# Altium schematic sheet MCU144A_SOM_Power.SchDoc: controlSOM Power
size 431 x 279 mm; Date: Not shown in title block; ApprovedBy: Not shown in title block; CheckedBy: Not shown in title block; Author: Not shown in title block; CompanyName: Not shown in title block; DrawnBy: Gustavo Martinez; Engineer: Not shown in title block; Organization: Not shown in title block; Address1: Not shown in title block; Address2: Not shown in title block; Address3: Not shown in title block; Address4: Not shown in title block; DocumentNumber: 6; Revision: Use project parameter SCH_Rev; SheetNumber: 5; SheetTotal: 8; PageSetup: Record=PageOptions¦CenterHorizontal=True¦CenterVertical=True¦PrintScale=1.00¦XCorrection=1.00¦YCorrection=1.00¦PrintKind=0¦BorderSize=5000000¦LeftOffset=0¦BottomOffset=0¦Orientation=2¦PaperLength=1000¦PaperWidth=1000¦Scale=100¦PaperSource=15¦PrintQuality=600¦MediaType=1¦DitherType=10¦PaperKind=Letter¦PrintScaleMode=1
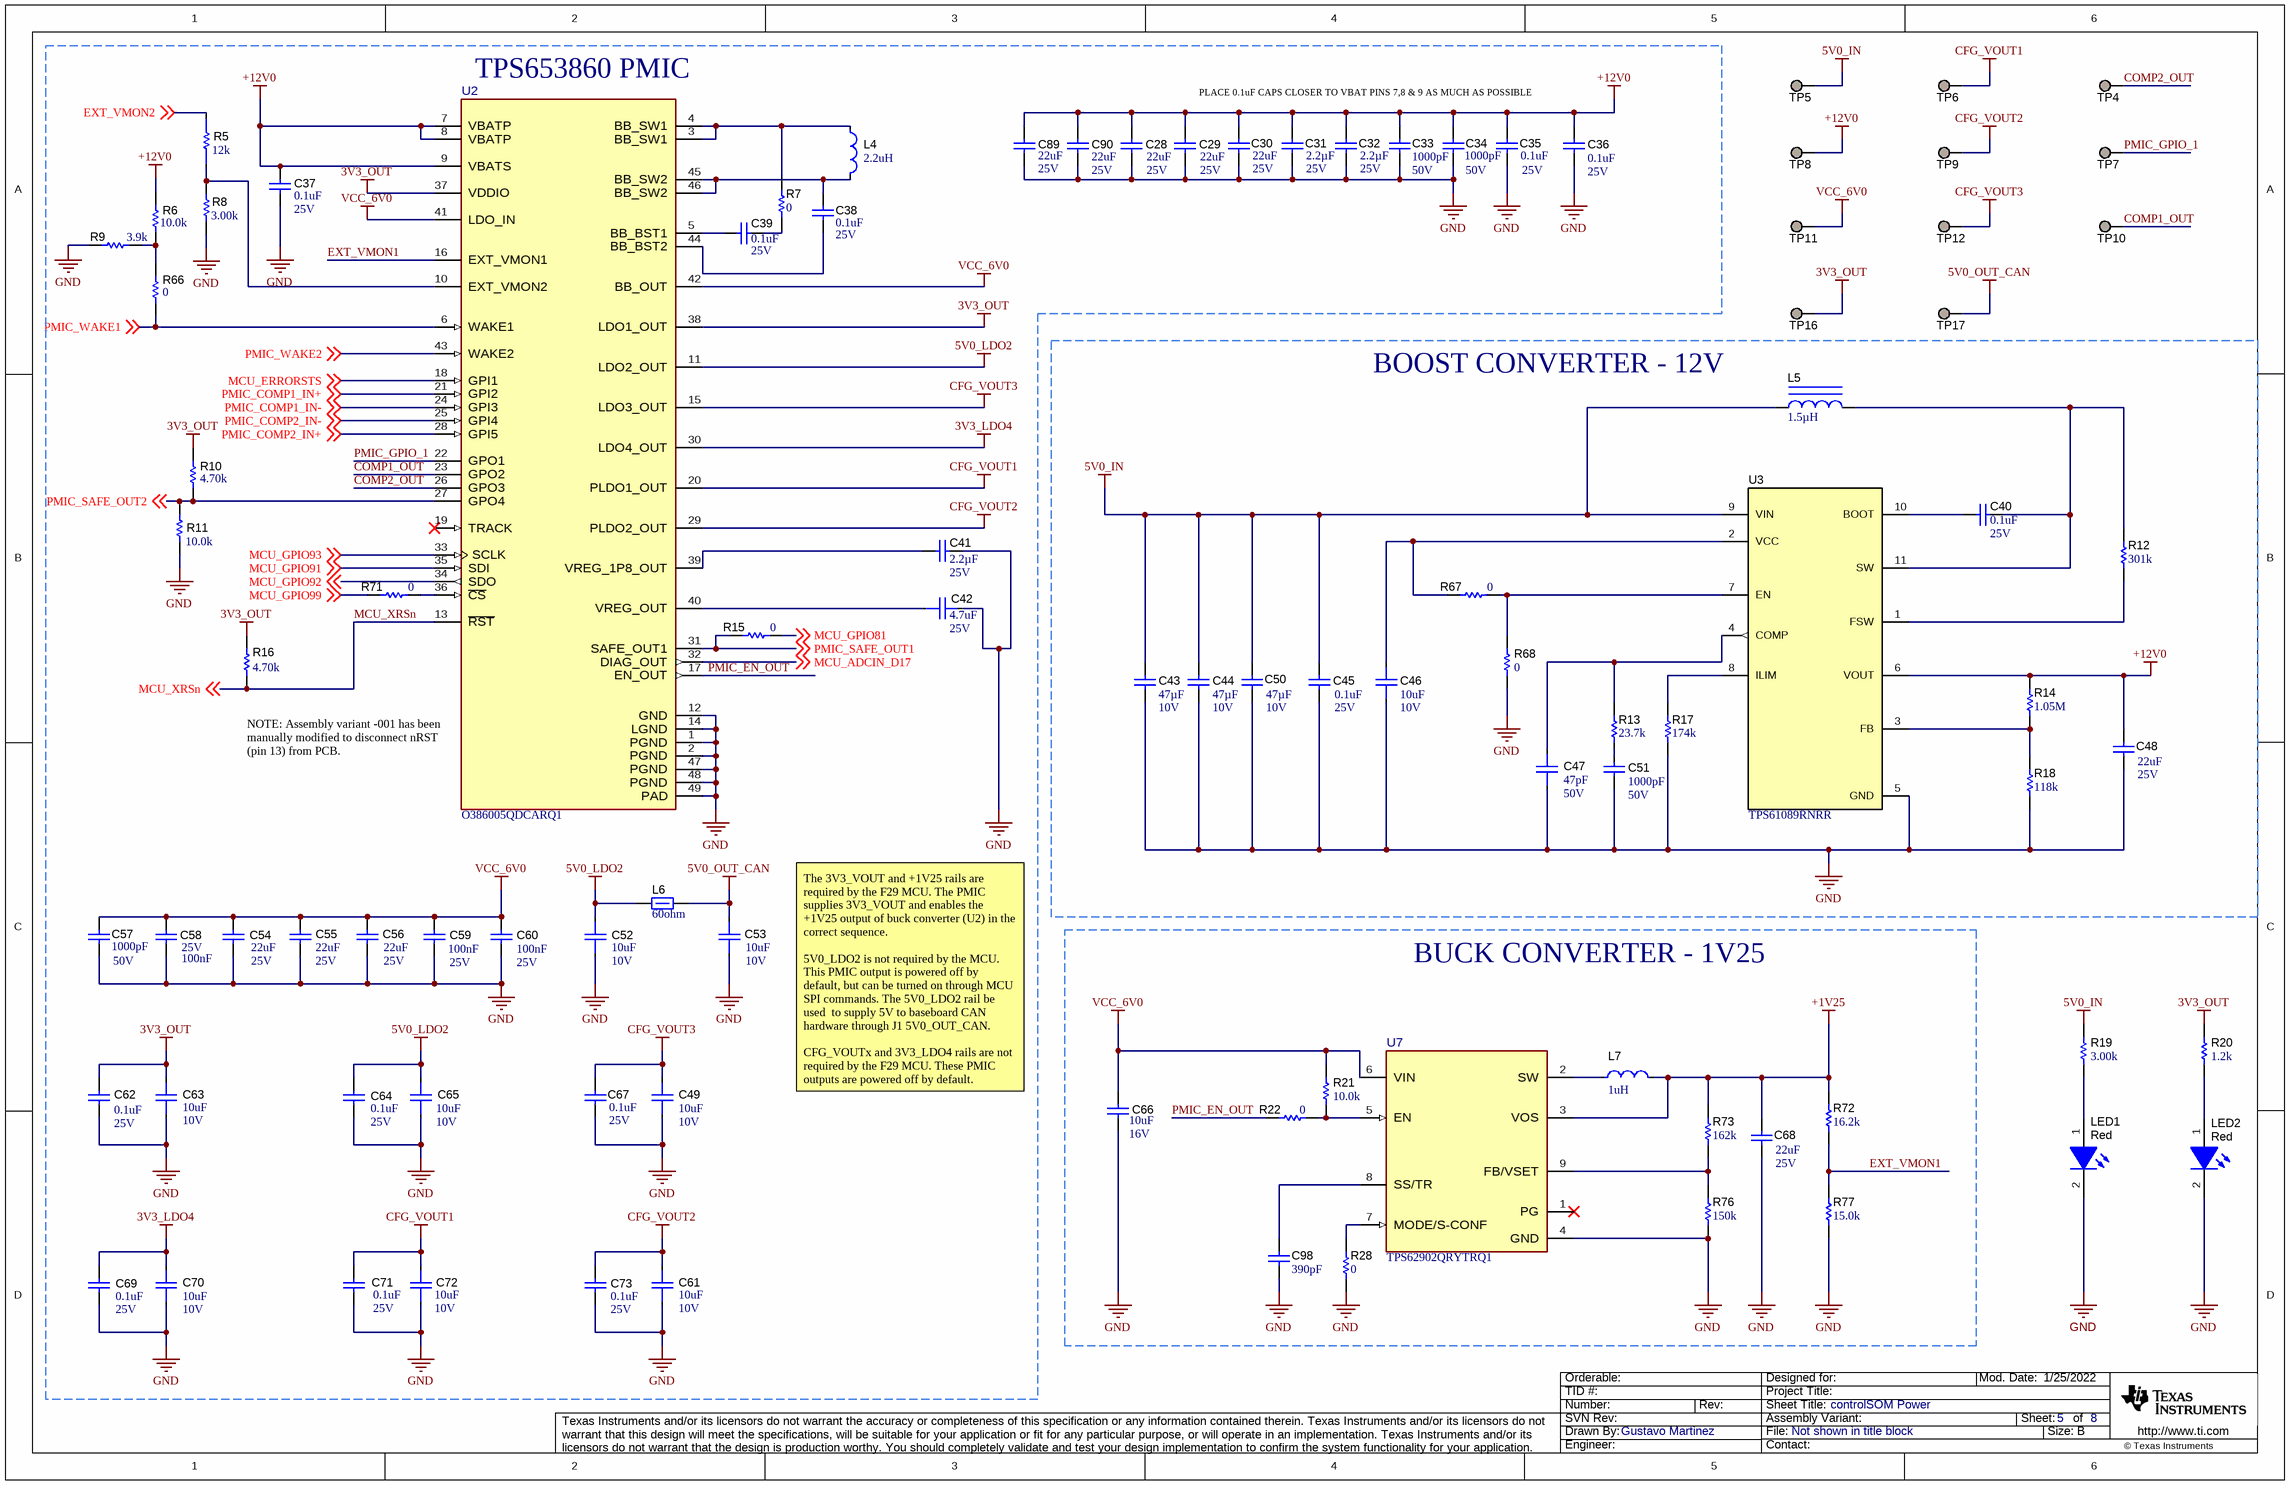
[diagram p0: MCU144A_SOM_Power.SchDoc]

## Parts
C28  VDC_V: 25V  ValueDisplayed: 22uF  [0805_HV]  (hidden comment: GRM21BR61E226ME44L)
C29  VDC_V: 25V  ValueDisplayed: 22uF  [0805_HV]  (hidden comment: GRM21BR61E226ME44L)
C30  VDC_V: 25V  ValueDisplayed: 22uF  [0805_HV]  (hidden comment: GRM21BR61E226ME44L)
C31  VDC_V: 25V  ValueDisplayed: 2.2µF  [0402]  (hidden comment: GRM155R61E225ME15D)
C32  VDC_V: 25V  ValueDisplayed: 2.2µF  [0402]  (hidden comment: GRM155R61E225ME15D)
C33  VDC_V: 50V  ValueDisplayed: 1000pF  [0402]  (hidden comment: GRM1555C1H102JA01D)
C34  VDC_V: 50V  ValueDisplayed: 1000pF  [0402]  (hidden comment: GRM1555C1H102JA01D)
C35  VDC_V: 25V  ValueDisplayed: 0.1uF  [0402]  (hidden comment: GRM155R71E104KE14D)
C36  VDC_V: 25V  ValueDisplayed: 0.1uF  [0402]  (hidden comment: GRM155R71E104KE14D)
C37  VDC_V: 25V  ValueDisplayed: 0.1uF  [0402]  (hidden comment: GRM155R71E104KE14D)
C38  VDC_V: 25V  ValueDisplayed: 0.1uF  [0402]  (hidden comment: GRM155R71E104KE14D)
C39  VDC_V: 25V  ValueDisplayed: 0.1uF  [0402]  (hidden comment: GRM155R71E104KE14D)
C40  Value2: 25V  ValueDisplayed: 0.1uF  [0402]  (hidden comment: GRM155R71E104KE14D)
C41  VDC_V: 25V  ValueDisplayed: 2.2µF  [0402]  (hidden comment: GRM155R61E225ME15D)
C42  ValueDisplayed: 4.7uF  VDC_V: 25V  [FP-GRM155C61E475ME15D_0402-MFG]  (hidden comment: GRM155C61E475ME15D)
C43  VDC_V: 10V  ValueDisplayed: 47µF  [0805_HV]  (hidden comment: GRM21BR61A476ME15L)
C44  VDC_V: 10V  ValueDisplayed: 47µF  [0805_HV]  (hidden comment: GRM21BR61A476ME15L)
C45  VDC_V: 25V  ValueDisplayed: 0.1uF  [0402]  (hidden comment: GRM155R71E104KE14D)
C46  VDC_V: 10V  ValueDisplayed: 10uF  [FP-GRM155R61A106ME18D_0402-MFG]  (hidden comment: GRM155R61A106ME18D)
C47  ValueDisplayed: 47pF  VDC_V: 50V  [FP-GJM1555C1H470JB01D_0402-MFG]  (hidden comment: GJM1555C1H470JB01D)
C48  VDC_V: 25V  ValueDisplayed: 22uF  [0805_HV]  (hidden comment: GRM21BR61E226ME44L)
C49  VDC_V: 10V  ValueDisplayed: 10uF  [FP-GRM155R61A106ME18D_0402-MFG]  (hidden comment: GRM155R61A106ME18D)
C50  VDC_V: 10V  ValueDisplayed: 47µF  [0805_HV]  (hidden comment: GRM21BR61A476ME15L)
C51  VDC_V: 50V  ValueDisplayed: 1000pF  [0402]  (hidden comment: GRM1555C1H102JA01D)
C52  VDC_V: 10V  ValueDisplayed: 10uF  [FP-GRM155R61A106ME18D_0402-MFG]  (hidden comment: GRM155R61A106ME18D)
C53  VDC_V: 10V  ValueDisplayed: 10uF  [FP-GRM155R61A106ME18D_0402-MFG]  (hidden comment: GRM155R61A106ME18D)
C54  VDC_V: 25V  ValueDisplayed: 22uF  [0805_HV]  (hidden comment: GRM21BR61E226ME44L)
C55  VDC_V: 25V  ValueDisplayed: 22uF  [0805_HV]  (hidden comment: GRM21BR61E226ME44L)
C56  VDC_V: 25V  ValueDisplayed: 22uF  [0805_HV]  (hidden comment: GRM21BR61E226ME44L)
C57  VDC_V: 50V  ValueDisplayed: 1000pF  [0402]  (hidden comment: GRM1555C1H102JA01D)
C58  Cap_F: 100nF  VDC_V: 25V  [0402]  (hidden comment: GRM155R71E104KE14D)
C59  Cap_F: 100nF  VDC_V: 25V  [0402]  (hidden comment: GRM155R71E104KE14D)
C60  Cap_F: 100nF  VDC_V: 25V  [0402]  (hidden comment: GRM155R71E104KE14D)
C61  VDC_V: 10V  ValueDisplayed: 10uF  [FP-GRM155R61A106ME18D_0402-MFG]  (hidden comment: GRM155R61A106ME18D)
C62  VDC_V: 25V  ValueDisplayed: 0.1uF  [0402]  (hidden comment: GRM155R71E104KE14D)
C63  VDC_V: 10V  ValueDisplayed: 10uF  [FP-GRM155R61A106ME18D_0402-MFG]  (hidden comment: GRM155R61A106ME18D)
C64  VDC_V: 25V  ValueDisplayed: 0.1uF  [0402]  (hidden comment: GRM155R71E104KE14D)
C65  VDC_V: 10V  ValueDisplayed: 10uF  [FP-GRM155R61A106ME18D_0402-MFG]  (hidden comment: GRM155R61A106ME18D)
C66  VDC_V: 16V  ValueDisplayed: 10uF  [0603]  (hidden comment: GRM188R61C106MAALD)
C67  VDC_V: 25V  ValueDisplayed: 0.1uF  [0402]  (hidden comment: GRM155R71E104KE14D)
C68  VDC_V: 25V  ValueDisplayed: 22uF  [0805_HV]  (hidden comment: GRM21BR61E226ME44L)
C69  VDC_V: 25V  ValueDisplayed: 0.1uF  [0402]  (hidden comment: GRM155R71E104KE14D)
C70  VDC_V: 10V  ValueDisplayed: 10uF  [FP-GRM155R61A106ME18D_0402-MFG]  (hidden comment: GRM155R61A106ME18D)
C71  VDC_V: 25V  ValueDisplayed: 0.1uF  [0402]  (hidden comment: GRM155R71E104KE14D)
C72  VDC_V: 10V  ValueDisplayed: 10uF  [FP-GRM155R61A106ME18D_0402-MFG]  (hidden comment: GRM155R61A106ME18D)
C73  VDC_V: 25V  ValueDisplayed: 0.1uF  [0402]  (hidden comment: GRM155R71E104KE14D)
C89  VDC_V: 25V  ValueDisplayed: 22uF  [0805_HV]  (hidden comment: GRM21BR61E226ME44L)
C90  VDC_V: 25V  ValueDisplayed: 22uF  [0805_HV]  (hidden comment: GRM21BR61E226ME44L)
C98  ValueDisplayed: 390pF  [0402]  (hidden comment: GCM155R71H391KA37D)
L4  value 2.2uH  [FP-SPM7054VT-2R2M-D_SMT_IND_7MM5_7MM0-MFG]  (hidden comment: SPM7054VT-2R2M-D)
L5  ValueDisplayed: 1.5µH  [DFE252012P]  (hidden comment: DFE252012P-1R5M=P2)
L6  60ohm  [0603]
L7  value 1uH  [FP-XGL4030-102MEC_SMD_IND_4MM0_4MM0-MFG]  (hidden comment: XGL4030-102MEC)
LED1  value Red  [APHHS1005_Red]  (hidden comment: APHHS1005SURCK)
LED2  value Red  [APHHS1005_Red]  (hidden comment: APHHS1005SURCK)
R5  value 12k  [FP-RC0402FR-0712KL_0402 (1005 Metric)-MFG]  (hidden comment: RC0402FR-0712KL)
R6  ValueDisplayed: 10.0k  [0402]  (hidden comment: AC0402FR-0710KL)
R7  ValueDisplayed: 0  [0402]  (hidden comment: CRCW04020000Z0ED)
R8  ValueDisplayed: 3.00k  [0402]  (hidden comment: RC0402FR-073KL)
R9  ValueDisplayed: 3.9k  [0402]  (hidden comment: CRCW04023K90JNED)
R10  value 4.70k  [0402]  (hidden comment: CRG0402F4K7)
R11  value 10.0k  [0402]  (hidden comment: AC0402FR-0710KL)
R12  ValueDisplayed: 301k  [0402]  (hidden comment: CRCW0402301KFKED)
R13  ValueDisplayed: 23.7k  [0402]  (hidden comment: CRCW040223K7FKED)
R14  ValueDisplayed: 1.05M  [0402]  (hidden comment: CRCW04021M05FKED)
R15  ValueDisplayed: 0  [0402]  (hidden comment: CRCW04020000Z0ED)
R16  ValueDisplayed: 4.70k  [0402]  (hidden comment: CRG0402F4K7)
R17  ValueDisplayed: 174k  [0402]  (hidden comment: CRCW0402174KFKED)
R18  ValueDisplayed: 118k  [0402]  (hidden comment: CRCW0402118KFKED)
R19  ValueDisplayed: 3.00k  [0402]  (hidden comment: RC0402FR-073KL)
R20  ValueDisplayed: 1.2k  [0402]  (hidden comment: CRCW04021K20JNED)
R21  value 10.0k  [0402]  (hidden comment: AC0402FR-0710KL)
R22  ValueDisplayed: 0  [0402]  (hidden comment: CRCW04020000Z0ED)
R28  ValueDisplayed: 0  [0402]  (hidden comment: CRCW04020000Z0ED)
R66  ValueDisplayed: 0  [0402]  (hidden comment: CRCW04020000Z0ED)
R67  ValueDisplayed: 0  [0402]  (hidden comment: CRCW04020000Z0ED)
R68  value 0  [0402]  (hidden comment: CRCW04020000Z0ED)
R71  ValueDisplayed: 0  [0402]  (hidden comment: CRCW04020000Z0ED)
R72  ValueDisplayed: 16.2k  [0402]  (hidden comment: CRCW040216K2FKED)
R73  ValueDisplayed: 162k  [0402]  (hidden comment: CRCW0402162KFKED)
R76  ValueDisplayed: 150k  [0402]  (hidden comment: CRCW0402150KFKED)
R77  ValueDisplayed: 15.0k  [0402]  (hidden comment: CRCW040215K0FKED)
TP4  TP_SM_1MM  [TP_SM_1MM]  (value not drawn)  (no BOM)
TP5  CMP-0078143-4  [TESTPOINT]  (value not drawn)  (no BOM)
TP6  TP_SM_1MM  [TP_SM_1MM]  (value not drawn)  (no BOM)
TP7  TP_SM_1MM  [TP_SM_1MM]  (value not drawn)  (no BOM)
TP8  CMP-0078143-4  [TESTPOINT]  (value not drawn)  (no BOM)
TP9  TP_SM_1MM  [TP_SM_1MM]  (value not drawn)  (no BOM)
TP10  TP_SM_1MM  [TP_SM_1MM]  (value not drawn)  (no BOM)
TP11  TP_SM_1MM  [TP_SM_1MM]  (value not drawn)  (no BOM)
TP12  TP_SM_1MM  [TP_SM_1MM]  (value not drawn)  (no BOM)
TP16  CMP-0078143-4  [TESTPOINT]  (value not drawn)  (no BOM)
TP17  CMP-0078143-4  [TESTPOINT]  (value not drawn)  (no BOM)
U2  O386005QDCARQ1  [DCA0048J-MFG]
U3  TPS61089RNRR  [RNR0011A]
U7  TPS62902QRYTRQ1  [RYT0009A-MFG]

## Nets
3V3_LDO4: C69.1 C70.2 U2.30(LDO4_OUT)
3V3_OUT: C62.1 C63.2 R10.2 R16.2 R20.2 TP16.1 U2.37(VDDIO) U2.38(LDO1_OUT)
5V0_IN: C43.1 C44.1 C45.1 C50.1 L5.1 R19.2 TP5.1 U3.9(VIN)
5V0_LDO2: C52.2 C64.1 C65.2 L6.1 U2.11(LDO2_OUT)
5V0_OUT_CAN: C53.2 L6.2 TP17.1
+1V25: C68.1 L7.2 R72.2 R73.2 U7.3(VOS)
+12V0: C28.1 C29.1 C30.1 C31.1 C32.1 C33.1 C34.1 C35.1 C36.1 C37.1 C48.1 C89.1 C90.1 R6.2 R14.2 TP8.1 U2.7(VBATP) U2.8(VBATP) U2.9(VBATS) U3.6(VOUT)
CFG_VOUT1: C71.1 C72.2 TP6.1 U2.20(PLDO1_OUT)
CFG_VOUT2: C61.2 C73.1 TP9.1 U2.29(PLDO2_OUT)
CFG_VOUT3: C49.2 C67.1 TP12.1 U2.15(LDO3_OUT)
GND: C28.2 C29.2 C30.2 C31.2 C32.2 C33.2 C34.2 C35.2 C36.2 C37.2 C41.1 C42.2 C43.2 C44.2 C45.2 C46.1 C47.1 C48.2 C49.1 C50.2 C51.2 C52.1 C53.1 C54.2 C55.2 C56.2 C57.2 C58.2 C59.2 C60.2 C61.1 C62.2 C63.1 C64.2 C65.1 C66.2 C67.2 C68.2 C69.2 C70.1 C71.2 C72.1 C73.2 C89.2 C90.2 C98.1 LED1.2(K) LED2.2(K) R8.1 R9.1 R11.1 R17.1 R18.1 R28.1 R68.1 R76.1 R77.1 U2.1(PGND) U2.2(PGND) U2.12(GND) U2.14(LGND) U2.47(PGND) U2.48(PGND) U2.49(PAD) U3.5(GND) U7.4(GND)
VCC_6V0: C54.1 C55.1 C56.1 C57.1 C58.1 C59.1 C60.1 C66.1 R21.2 TP11.1 U2.41(LDO_IN) U2.42(BB_OUT) U7.6(VIN)
COMP1_OUT: TP10.1 U2.23(GPO2)
COMP2_OUT: TP4.1 U2.26(GPO3)
EXT_VMON1: R72.1 R77.2 U2.16(EXT_VMON1)
EXT_VMON2: R5.2 ; off-sheet EXT_VMON2
MCU_ADCIN_D17: U2.32(DIAG_OUT) ; off-sheet MCU_ADCIN_D17
MCU_ERRORSTS: U2.18(GPI1) ; off-sheet MCU_ERRORSTS
MCU_GPIO81: R15.2 ; off-sheet MCU_GPIO81
MCU_GPIO91: U2.35(SDI) ; off-sheet MCU_GPIO91
MCU_GPIO92: U2.34(SDO) ; off-sheet MCU_GPIO92
MCU_GPIO93: U2.33(SCLK) ; off-sheet MCU_GPIO93
MCU_GPIO99: R71.1 ; off-sheet MCU_GPIO99
MCU_XRSn: R16.1 U2.13(~{RST}) ; off-sheet MCU_XRSn
PMIC_COMP1_IN+: U2.21(GPI2) ; off-sheet PMIC_COMP1_IN+
PMIC_COMP1_IN-: U2.24(GPI3) ; off-sheet PMIC_COMP1_IN-
PMIC_COMP2_IN+: U2.28(GPI5) ; off-sheet PMIC_COMP2_IN+
PMIC_COMP2_IN-: U2.25(GPI4) ; off-sheet PMIC_COMP2_IN-
PMIC_EN_OUT: R22.1 U2.17(EN_OUT)
PMIC_GPIO_1: TP7.1 U2.22(GPO1)
PMIC_SAFE_OUT1: R15.1 U2.31(SAFE_OUT1) ; off-sheet PMIC_SAFE_OUT1
PMIC_SAFE_OUT2: R10.1 R11.2 U2.27(GPO4) ; off-sheet PMIC_SAFE_OUT2
PMIC_WAKE1: R66.1 U2.6(WAKE1) ; off-sheet PMIC_WAKE1
PMIC_WAKE2: U2.43(WAKE2) ; off-sheet PMIC_WAKE2
NetC38_1: C38.1 L4.2 U2.45(BB_SW2) U2.46(BB_SW2)
NetC38_2: C38.2 U2.44(BB_BST2)
NetC39_1: C39.1 R7.1
NetC39_2: C39.2 U2.5(BB_BST1)
NetC40_1: C40.1 U3.10(BOOT)
NetC40_2: C40.2 L5.2 R12.2 U3.11(SW)
NetC41_2: C41.2 U2.39(VREG_1P8_OUT)
NetC42_1: C42.1 U2.40(VREG_OUT)
NetC46_2: C46.2 R67.2 U3.2(VCC)
NetC47_2: C47.2 R13.2 U3.4(COMP)
NetC51_1: C51.1 R13.1
NetC98_2: C98.2 U7.8(SS/TR)
NetL4_1: L4.1 R7.2 U2.3(BB_SW1) U2.4(BB_SW1)
NetL7_1: L7.1 U7.2(SW)
NetLED1_1: LED1.1(A) R19.1
NetLED2_1: LED2.1(A) R20.1
NetR5_1: R5.1 R8.2 U2.10(EXT_VMON2)
NetR6_1: R6.1 R9.2 R66.2
NetR12_1: R12.1 U3.1(FSW)
NetR14_1: R14.1 R18.2 U3.3(FB)
NetR17_2: R17.2 U3.8(ILIM)
NetR21_1: R21.1 R22.2 U7.5(EN)
NetR28_2: R28.2 U7.7(MODE/S-CONF)
NetR67_1: R67.1 R68.2 U3.7(EN)
NetR71_2: R71.2 U2.36(~{CS})
NetR73_1: R73.1 R76.2 U7.9(FB/VSET)

Not connected (* = marked no-connect by the designer): U2 19(TRACK)*; U7 1(PG)*

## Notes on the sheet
- (near U2) TPS653860 PMIC
- PLACE 0.1uF CAPS CLOSER TO VBAT PINS 7,8 & 9 AS MUCH AS POSSIBLE
- BOOST CONVERTER - 12V
- (near R71) MCU_XRSn
- (near U2) NOTE: Assembly variant -001 has been manually modified to disconnect nRST (pin 13) from PCB.
- BUCK CONVERTER - 1V25
- The 3V3_VOUT and +1V25 rails are required by the F29 MCU. The PMIC supplies 3V3_VOUT and enables the +1V25 output of buck converter (U2) in the correct sequence.
  5V0_LDO2 is not required by the MCU. This PMIC output is powered off by default, but can be turned on through MCU SPI commands. The 5V0_LDO2 rail be used  to supply 5V to baseboard CAN hardware through J1 5V0_OUT_CAN.
  CFG_VOUTx and 3V3_LDO4 rails are not required by the F29 MCU. These PMIC outputs are powered off by default.

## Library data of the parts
C28-C30 C48 C68 C89 C90 = CMP-0008305-2: CAP, CERM, 22 uF, 25 V, +/- 20%, X5R, 0805; Manufacturer: MuRata; TaMin_C: -55°C; Polarized: N; SizeAreaWB_mm2: 6.75; Value1: Unknown; U/M: EA; Value: 22uF; TaMax_C: 85°C; SizeZ_mm: 1.45; SizeX_mm: 2; SizeY_mm: 1.25; Cap_Case: 0805; SizeArea_mm2: 2.5; Cap_F: 22µF; AEC Category: Q200
C31 C32 C41 = CMP-0081010-1: CAP, CERM, 2.2 µF, 25 V,+/- 20%, X5R, 0402; Manufacturer: MuRata; SizeAreaWB_mm2: 3; SizeArea_mm2: 0.5; AEC Qualified: N; AEC Category: Q200; Value: 2.2uF; TaMax_C: 85°C; SizeZ_mm: 0.6; TaMin_C: -55°C; U/M: EA; SizeX_mm: 1
C33 C34 C51 C57 = CMP-0006412-2: CAP, CERM, 1000 pF, 50 V, +/- 5%, C0G/NP0, 0402; Manufacturer: MuRata; TaMin_C: -55°C; Polarized: N; SizeAreaWB_mm2: 3; Value1: Unknown; U/M: EA; Value: 1000pF; TaMax_C: 125°C; SizeZ_mm: 0.6; SizeX_mm: 1; SizeY_mm: 0.5; Cap_F: 1nF; AEC Category: Q200
C35-C40 C45 C62 C64 C67 C69 C71 C73 = CMP-0006659-2: CAP, CERM, 0.1 uF, 25 V, +/- 10%, X7R, 0402; Manufacturer: MuRata; TaMin_C: -55°C; Polarized: N; SizeAreaWB_mm2: 3; Value1: Unknown; U/M: EA; Value: 0.1uF; TaMax_C: 125°C; SizeZ_mm: 0.6; SizeX_mm: 1; SizeY_mm: 0.5; Cap_F: 100nF; AEC Category: Q200
C42 = CMP-0120206-1: 4.7 µF ±20% 25V Ceramic Capacitor X5S 0402 (1005 Metric); Manufacturer: Murata; AEC Qualified: No; Cap_F: 4.7µF; SizeZ_mm: 0.7mm; TempCo: 22%; Value: 4.7µF
C43 C44 C50 = CMP-0078699-1: CAP, CERM, 47 µF, 10 V,+/- 20%, X5R, 0805; Manufacturer: MuRata; TaMin_C: -55°C; Polarized: N; Green_Lifecycle: Active; SizeAreaWB_mm2: 6.75; Green_REACh: Passed; U/M: EA; Value: 47uF; TaMax_C: 85°C; SizeZ_mm: 1.45; SizeX_mm: 2; SizeY_mm: 1.25; Cap_Case: 0805; SizeArea_mm2: 2.5; AEC Category: Q200
C46 C49 C52 C53 C61 C63 C65 C70 C72 = CMP-0120207-1: 10 µF ±20% 10V Ceramic Capacitor X5R 0402 (1005 Metric); Manufacturer: Murata; Cap_F: 10µF; TempCo: 15%; SizeZ_mm: 0.7mm; Value: 10µF; AEC Qualified: No
C47 = CMP-0120205-1: Multi-Layer Ceramic Capacitor 47pF C0G  ±5% 0402 Paper T/R; Manufacturer: Murata; AEC Qualified: No; SizeZ_mm: 0.55mm; TempCo: 30ppm/°C
C54-C56 = CMP-0008305-2: CAP, CERM, 22 uF, 25 V, +/- 20%, X5R, 0805; Manufacturer: MuRata; SizeZ_mm: 1.45; AEC Qualified: N; Value: 22uF; Cap_F: 22µF; AEC Category: Q200; Cap_Case: 0805; SizeArea_mm2: 2.5; SizeAreaWB_mm2: 6.75; SizeX_mm: 2; SizeY_mm: 1.25; TaMax_C: 85°C; TaMin_C: -55°C; U/M: EA; Value1: Unknown
C58-C60 = CMP-0006659-2: CAP, CERM, 0.1 uF, 25 V, +/- 10%, X7R, 0402; Manufacturer: MuRata; TaMin_C: -55°C; Polarized: N; SizeAreaWB_mm2: 3; Value1: Unknown; U/M: EA; Value: 0.1uF; TaMax_C: 125°C; SizeZ_mm: 0.6; SizeX_mm: 1; SizeY_mm: 0.5; AEC Category: Q200
C66 = CMP-0007336-5: CAP, CERM, 10 uF, 16 V, +/- 20%, X5R, 0603; Manufacturer: MuRata; TaMin_C: -55°C; Polarized: N; SizeAreaWB_mm2: 4.68; Value1: Unknown; U/M: EA; Value: 10uF; TaMax_C: 85°C; SizeZ_mm: 1; SizeX_mm: 1.6; SizeY_mm: 0.8; SizeArea_mm2: 1.28; Cap_F: 10µF; AEC Category: Q200
C98 = CMP-0080703-2: CAP, CERM, 390 pF, 50 V,+/- 10%, X7R, AEC-Q200 Grade 1, 0402; Manufacturer: MuRata; SizeX_mm: 1; SizeZ_mm: 0.6; SizeY_mm: 0.5; AEC Qualified: Y; Value: 390pF; Polarized: N; AEC Category: Q200; TaMax_C: 125°C; VDC_V: 50V; TaMin_C: -55°C; SizeAreaWB_mm2: 3; U/M: EA
L4 = CMP-0096709-1: Inductor Power Shielded Wirewound 2.2uH 20% 100KHz Metal 12A 0.00814Ohm DCR Automotive T/R; Manufacturer: TDK; Ind_H: 2.2µH; AEC Grade: Grade 0; Isat: 14.1A; SizeZ_mm: 5.4mm; AEC Qualified: Yes; Shrouded: true; Material: Metal Composite; DCR_ohm: 8.14m
L5 = CMP-0082609-1: Inductor, Shielded, Metal Composite, 1.5 µH, 2.6 A, 0.06 ohm, SMD; Manufacturer: MuRata; Isat: 3.5A @ 30% inductance drop; Irms: 2.6A @ 40C rise; SizeAreaWB_mm2: 10.5; DCR_ohm: 0.06; Value: 1.5uH; Imax_A: 2.6A; SizeZ_mm: 1.2; SizeX_mm: 2.5; SizeY_mm: 2; SizeArea_mm2: 5; AEC Qualified: N; AEC Category: Q200
L6 = CMP-0003173-2: Ferrite Bead, 60 ohm @ 100 MHz, 3 A, 0603; Manufacturer: Wurth Elektronik; PartNumber: 742792602; Ztyp@1GHz_Ohm: 110.436; ZTyp@100MHz_Ohm: 60; SizeAreaWB_mm2: 4.68; DCR_ohm: 0.04; Value1: 0.04 ohm; Imax_A: 3A; SizeZ_mm: 1; SizeX_mm: 1.6; SizeY_mm: 0.8; SizeArea_mm2: 1.28
L7 = CMP-0090842-1: Power Inductor, shielded, composite, 1uH 20% tol, DCR 7.2mOhms, SRF 65MHz, Isat 4.8A, Irms 13A, AEC-Q200; Manufacturer: Coilcraft; TaMin_C: -40°C; TaMax_C: +125°C; Test Frequency: 1MHz; DCR_ohm: 7.2m; AEC Grade: Grade 1; SizeZ_mm: 3.1mm; AEC Qualified: Yes; Shrouded: true; Ind_H: 1µH
LED1 LED2 = CMP-0067681-2: LED, Red, SMD; Manufacturer: Kingbright; Vf_V: 1.95V; SizeAreaWB_mm2: 3.0; Tjmax_C: 85°C; SizeX_mm: 1.0; Io_A: 20mA; SizeArea_mm2: 0.5; Vr_V: 5V; Value1: 0.075W; SizeZ_mm: 0.6; Angle: 120.0; Ir_A: 10µA; Power_TotalModule: 75mW
R5 = CMP-0092615-1: 12 kOhms ±1% 0.063W, 1/16W Chip Resistor 0402 (1005 Metric) Moisture Resistant Thick Film; Manufacturer: Yageo; SizeZ_mm: 0.4mm; VDC_V: 50V; TempCo: 100ppm/°C; AEC Qualified: No; Power_W: 63mW
R6 = CMP-0077731-1: RES, 10.0 k, 1%, 0.063 W, AEC-Q200 Grade 0, 0402; Manufacturer: Yageo America; Power_W: 63mW; TempCo: 100 ppm/C; Value_Code: 10k0; U/M: EA; Value: 10.0k; EIA_Code: E96; Res_ohm: 10k; SizeX_mm: 1.0; SizeY_mm: 0.5; SizeZ_mm: 0.6; Value2: 0.063W; AEC Qualified: Y; VDC_V: 50V; AEC Grade: 0; AEC Category: Q200
R7 R15 R22 R28 R66 R67 R71 = CMP-0026822-3: RES, 0, 5%, 0.063 W, AEC-Q200 Grade 0, 0402; Manufacturer: Vishay-Dale; Power_W: 63mW; TempCo: 200 ppm/C; Value_Code: 0000; Value: 0; EIA_Code: E24; SizeX_mm: 1; SizeY_mm: 0.5; SizeZ_mm: 0.6; Value2: 0.063W; AEC Qualified: Y; VDC_V: 50V; AEC Category: Q200
R8 R19 = CMP-0026733-1: RES, 3.00 k, 1%, 0.0625 W, 0402; Manufacturer: Yageo America; Power_W: 62.5mW; TempCo: 100 ppm/C; Value_Code: 3k00; U/M: EA; Value: 3.00k; Res_ohm: 3k; SizeX_mm: 1; SizeY_mm: 0.5; SizeZ_mm: 0.6; AEC Qualified: N; VDC_V: 50V; AEC Category: Q200
R9 = CMP-0026920-5: RES, 3.9 k, 5%, 0.063 W, AEC-Q200 Grade 0, 0402; Manufacturer: Vishay-Dale; Power_W: 63mW; TempCo: 200 ppm/C; Value_Code: 3k90; Value: 3.9k; EIA_Code: E24; SizeX_mm: 1; SizeY_mm: 0.5; SizeZ_mm: 0.6; Value2: 0.063W; AEC Qualified: Y; VDC_V: 50V; AEC Category: Q200; AEC Grade: 0
R10 = CMP-0026631-1: RES, 4.70 k, 1%, 0.063 W, 0402; Manufacturer: TE Connectivity; Power_W: 63mW; TempCo: 100 ppm/C; Value_Code: 4k70; U/M: EA; Res_ohm: 4.7k; SizeX_mm: 1; SizeY_mm: 0.5; SizeZ_mm: 0.6; Value2: 0.063W; AEC Qualified: N; AEC Category: Q200
R11 R21 = CMP-0077731-1: RES, 10.0 k, 1%, 0.063 W, AEC-Q200 Grade 0, 0402; Manufacturer: Yageo America; Power_W: 63mW; TempCo: 100 ppm/C; Value_Code: 10k0; U/M: EA; EIA_Code: E96; Res_ohm: 10k; SizeX_mm: 1.0; SizeY_mm: 0.5; SizeZ_mm: 0.6; Value2: 0.063W; AEC Qualified: Y; VDC_V: 50V; AEC Grade: 0; AEC Category: Q200
R12 = CMP-0026280-2: RES, 301 k, 1%, 0.063 W, AEC-Q200 Grade 0, 0402; Manufacturer: Vishay-Dale; Power_W: 63mW; TempCo: 100 ppm/C; Value: 301k; EIA_Code: E96; SizeX_mm: 1; SizeY_mm: 0.5; SizeZ_mm: 0.6; Value2: 0.063W; AEC Qualified: Y; VDC_V: 50V; AEC Category: Q200; AEC Grade: 0
R13 = CMP-0026187-2: RES, 23.7 k, 1%, 0.063 W, AEC-Q200 Grade 0, 0402; Manufacturer: Vishay-Dale; Power_W: 63mW; TempCo: 100 ppm/C; Value_Code: 23k7; Value: 23.7k; EIA_Code: E96; SizeX_mm: 1; SizeY_mm: 0.5; SizeZ_mm: 0.6; Value2: 0.063W; AEC Qualified: Y; VDC_V: 50V; AEC Category: Q200; AEC Grade: 0
R14 = CMP-0026102-2: RES, 1.05 M, 1%, 0.063 W, AEC-Q200 Grade 0, 0402; Manufacturer: Vishay-Dale; Power_W: 63mW; TempCo: 100 ppm/C; Value_Code: 1M05; Value: 1.05Meg; EIA_Code: E96; SizeX_mm: 1; SizeY_mm: 0.5; SizeZ_mm: 0.6; Value2: 0.063W; AEC Qualified: Y; VDC_V: 50V; AEC Category: Q200; AEC Grade: 0
R16 = CMP-0026631-1: RES, 4.70 k, 1%, 0.063 W, 0402; Manufacturer: TE Connectivity; Power_W: 63mW; TempCo: 100 ppm/C; Value_Code: 4k70; U/M: EA; Value: 4.70k; Res_ohm: 4.7k; SizeX_mm: 1; SizeY_mm: 0.5; SizeZ_mm: 0.6; Value2: 0.063W; AEC Qualified: N; AEC Category: Q200
R17 = CMP-0026046-3: RES, 174 k, 1%, 0.063 W, AEC-Q200 Grade 0, 0402; Manufacturer: Vishay-Dale; Power_W: 63mW; TempCo: 100 ppm/C; Value: 174k; EIA_Code: E96; SizeX_mm: 1; SizeY_mm: 0.5; SizeZ_mm: 0.6; Value2: 0.063W; AEC Qualified: Y; VDC_V: 50V; AEC Category: Q200; AEC Grade: 0
R18 = CMP-0025973-3: RES, 118 k, 1%, 0.063 W, AEC-Q200 Grade 0, 0402; Manufacturer: Vishay-Dale; Power_W: 63mW; TempCo: 100 ppm/C; Value: 118k; EIA_Code: E96; SizeX_mm: 1; SizeY_mm: 0.5; SizeZ_mm: 0.6; Value2: 0.063W; AEC Qualified: Y; VDC_V: 50V; AEC Category: Q200; AEC Grade: 0
R20 = CMP-0026854-5: RES, 1.2 k, 5%, 0.063 W, AEC-Q200 Grade 0, 0402; Manufacturer: Vishay-Dale; Power_W: 63mW; TempCo: 200 ppm/C; Value_Code: 1k20; Value: 1.2k; EIA_Code: E24; SizeX_mm: 1; SizeY_mm: 0.5; SizeZ_mm: 0.6; Value2: 0.063W; AEC Qualified: Y; VDC_V: 50V; AEC Category: Q200; AEC Grade: 0
R68 = CMP-0026822-3: RES, 0, 5%, 0.063 W, AEC-Q200 Grade 0, 0402; Manufacturer: Vishay-Dale; Power_W: 63mW; TempCo: 200 ppm/C; Value_Code: 0000; EIA_Code: E24; SizeX_mm: 1; SizeY_mm: 0.5; SizeZ_mm: 0.6; Value2: 0.063W; AEC Qualified: Y; VDC_V: 50V; AEC Category: Q200
R72 = CMP-0026040-3: RES, 16.2 k, 1%, 0.063 W, AEC-Q200 Grade 0, 0402; Manufacturer: Vishay-Dale; Power_W: 63mW; TempCo: 100 ppm/C; Value_Code: 16k2; Value: 16.2k; EIA_Code: E96; SizeX_mm: 1; SizeY_mm: 0.5; SizeZ_mm: 0.6; Value2: 0.063W; AEC Qualified: Y; VDC_V: 50V; AEC Category: Q200; AEC Grade: 0
R73 = CMP-0026034-3: RES, 162 k, 1%, 0.063 W, AEC-Q200 Grade 0, 0402; Manufacturer: Vishay-Dale; Power_W: 63mW; TempCo: 100 ppm/C; Value: 162k; EIA_Code: E96; SizeX_mm: 1; SizeY_mm: 0.5; SizeZ_mm: 0.6; Value2: 0.063W; AEC Qualified: Y; VDC_V: 50V; AEC Category: Q200; AEC Grade: 0
R76 = CMP-0026021-3: RES, 150 k, 1%, 0.063 W, AEC-Q200 Grade 0, 0402; Manufacturer: Vishay-Dale; Power_W: 63mW; TempCo: 100 ppm/C; Value: 150k; EIA_Code: E96; SizeX_mm: 1; SizeY_mm: 0.5; SizeZ_mm: 0.6; Value2: 0.063W; AEC Qualified: Y; VDC_V: 50V; AEC Category: Q200; AEC Grade: 0
R77 = CMP-0026027-3: RES, 15.0 k, 1%, 0.063 W, AEC-Q200 Grade 0, 0402; Manufacturer: Vishay-Dale; Power_W: 63mW; TempCo: 100 ppm/C; Value_Code: 15k0; Value: 15.0k; EIA_Code: E96; Res_ohm: 15k; SizeX_mm: 1; SizeY_mm: 0.5; SizeZ_mm: 0.6; Value2: 0.063W; AEC Qualified: Y; VDC_V: 50V; AEC Category: Q200; AEC Grade: 0
TP4 TP6 TP7 TP9-TP12 = CMP-0003825-1: 1mm Test Point, SMT; Manufacturer: Any
TP5 TP8 TP16 TP17 = CMP-0078143-4: TEST POINT.  No entry in BOM.
U2 = CMP-0095884-2: Power Management IC For Safety-Relevant Applications HTSSOP48 5 Outputs 4 LDO and 1 Synchronous Buck-Boost Regulator; Manufacturer: Texas Instruments; SizeZ_mm: 1.2mm; AEC Qualified: Yes; Standoff Height: 0.05mm; Max Supply Voltage: 28V; TaMin_C: -40°C; AEC Grade: Grade 1; TJmax_C: +150°C; Min Supply Voltage: 2.3V; Number Of Outputs: 7; TaMax_C: +125°C; AEC Category: Q200
U3 = CMP-0074067-1: 12.6-V, 7-A Fully-Integrated Synchronous Boost Converters in 2.0-mm x 2.5-mm VQFN Package, RNR0011A (VQFN-HR-11); Alternate PartNumber: TPS61089RNRT; Alternate Manufacturer: Texas Instruments; SizeAreaWB_mm2: 10.5; U/M: EA; SizeZ_mm: 1.0; SizeX_mm: 2.5; SizeY_mm: 2.0; SizeArea_mm2: 5.0; CompType: IC
U7 = CMP-0121948-1: 3-V to 18-V, 2-A, Automotive Low IQ Buck Converter with +165°C TJ; Manufacturer: Texas Instruments; SizeZ_mm: 1.05mm; AEC Qualified: Yes; AEC Grade: Grade 1; Max Duty Cycle: 100%; Max Supply Voltage: 18V; Min Supply Voltage: 3V; Nominal Supply Current: 8mA; Number Of Outputs: 1; Output Type: AdjustableProgrammable; Output Voltage: 0.4-5.5V; Standoff Height: 0mm; Switching Frequency: 1/2.5MHz; TaMax_C: +125°C; TaMin_C: -40°C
